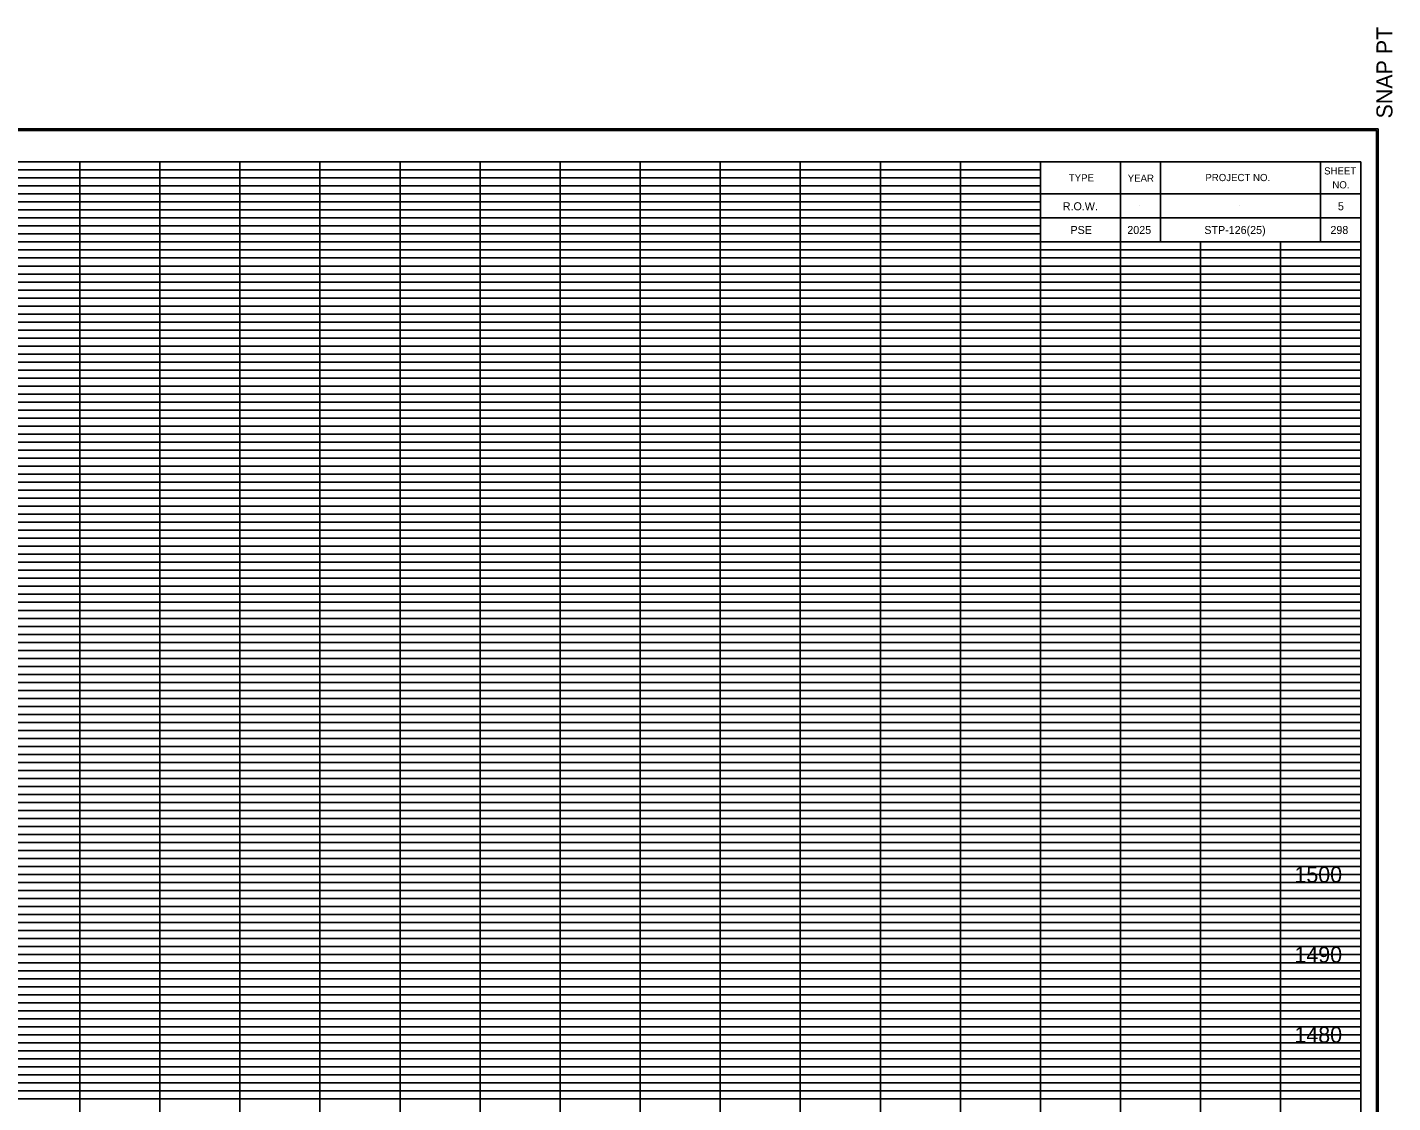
# Model space of a CAD drawing. Extents: x 980 to 2064, y 978 to 2267.
# Drawn here: x 1153.4 to 1324, y 2132.5 to 2266.8 of the extents above; entities that cross this region are included whole.
import ezdxf

# ---------------------------------------------------------------- set-up
doc = ezdxf.new("R2010")
doc.units = 0
for name, color, linetype in [('Default', 7, 'Continuous'), ('DESIGN - SCRATCH - User 1', 7, 'Continuous'), ('DESIGN - SHEET - Corner Text', 7, 'Continuous'), ('DESIGN - SHEET - Light Grid', 7, 'Continuous'), ('DESIGN - SHEET - Linework', 7, 'Continuous'), ('DESIGN - SHEET - Plot Shape', 7, 'Continuous')]:
    doc.layers.add(name, color=color, linetype=linetype)

# ---------------------------------------------------------------- blocks, each defined once
blk = doc.blocks.new('XSTSHT')
at = {"layer": 'DESIGN - SCRATCH - User 1'}
for p, q in [((28.5, 20.45), (28.5, 20.45)), ((29.24, 20.45), (29.24, 20.45)), ((30.49, 20.45), (30.49, 20.45)), ((31.74, 20.45), (31.74, 20.45)), ((28.5, 20.15), (28.5, 20.15)), ((29.24, 20.15), (29.24, 20.15)), ((30.49, 20.15), (30.49, 20.15)), ((31.74, 20.15), (31.74, 20.15))]:
    blk.add_line(p, q, dxfattribs=at)
at = {"layer": 'DESIGN - SHEET - Light Grid'}
for p, q in [((8, 20.9), (16, 20.9)), ((16, 20.9), (24, 20.9)), ((24, 20.9), (28, 20.9)), ((8, 20.8), (16, 20.8)), ((8, 20.7), (16, 20.7)), ((16, 20.8), (24, 20.8)), ((16, 20.7), (24, 20.7)), ((24, 20.8), (28, 20.8)), ((24, 20.7), (28, 20.7)), ((8, 20.6), (16, 20.6)), ((8, 20.5), (16, 20.5)), ((16, 20.6), (24, 20.6)), ((16, 20.5), (24, 20.5)), ((24, 20.6), (28, 20.6)), ((24, 20.5), (28, 20.5)), ((8, 20.4), (16, 20.4)), ((8, 20.3), (16, 20.3)), ((16, 20.4), (24, 20.4)), ((16, 20.3), (24, 20.3)), ((24, 20.4), (28, 20.4)), ((24, 20.3), (28, 20.3)), ((8, 20.2), (16, 20.2)), ((16, 20.2), (24, 20.2)), ((24, 20.2), (28, 20.2)), ((8, 20.1), (16, 20.1)), ((16, 20.1), (24, 20.1)), ((24, 20.1), (28, 20.1)), ((8, 19.9), (16, 19.9)), ((8, 19.8), (16, 19.8)), ((16, 19.9), (24, 19.9)), ((16, 19.8), (24, 19.8)), ((24, 19.9), (32, 19.9)), ((24, 19.8), (32, 19.8)), ((8, 19.7), (16, 19.7)), ((16, 19.7), (24, 19.7)), ((24, 19.7), (32, 19.7)), ((8, 19.6), (16, 19.6)), ((8, 19.5), (16, 19.5)), ((16, 19.6), (24, 19.6)), ((16, 19.5), (24, 19.5)), ((24, 19.6), (32, 19.6)), ((24, 19.5), (32, 19.5)), ((8, 19.4), (16, 19.4)), ((8, 19.3), (16, 19.3)), ((16, 19.4), (24, 19.4)), ((16, 19.3), (24, 19.3)), ((24, 19.4), (32, 19.4)), ((24, 19.3), (32, 19.3)), ((8, 19.2), (16, 19.2)), ((16, 19.2), (24, 19.2)), ((24, 19.2), (32, 19.2)), ((8, 19.1), (16, 19.1)), ((16, 19.1), (24, 19.1)), ((24, 19.1), (32, 19.1)), ((8, 18.9), (16, 18.9)), ((8, 18.8), (16, 18.8)), ((16, 18.9), (24, 18.9)), ((16, 18.8), (24, 18.8)), ((24, 18.9), (32, 18.9)), ((24, 18.8), (32, 18.8)), ((8, 18.7), (16, 18.7)), ((8, 18.6), (16, 18.6)), ((16, 18.7), (24, 18.7)), ((16, 18.6), (24, 18.6)), ((24, 18.7), (32, 18.7)), ((24, 18.6), (32, 18.6)), ((8, 18.5), (16, 18.5)), ((16, 18.5), (24, 18.5)), ((24, 18.5), (32, 18.5)), ((8, 18.4), (16, 18.4)), ((8, 18.3), (16, 18.3)), ((16, 18.4), (24, 18.4)), ((16, 18.3), (24, 18.3)), ((24, 18.4), (32, 18.4)), ((24, 18.3), (32, 18.3)), ((8, 18.2), (16, 18.2)), ((8, 18.1), (16, 18.1)), ((16, 18.2), (24, 18.2)), ((16, 18.1), (24, 18.1)), ((24, 18.2), (32, 18.2)), ((24, 18.1), (32, 18.1)), ((8, 17.9), (16, 17.9)), ((8, 17.8), (16, 17.8)), ((16, 17.9), (24, 17.9)), ((16, 17.8), (24, 17.8)), ((24, 17.9), (32, 17.9)), ((24, 17.8), (32, 17.8)), ((8, 17.7), (16, 17.7)), ((8, 17.6), (16, 17.6)), ((16, 17.7), (24, 17.7)), ((16, 17.6), (24, 17.6)), ((24, 17.7), (32, 17.7)), ((24, 17.6), (32, 17.6)), ((8, 17.5), (16, 17.5)), ((8, 17.4), (16, 17.4)), ((16, 17.5), (24, 17.5)), ((16, 17.4), (24, 17.4)), ((24, 17.5), (32, 17.5)), ((24, 17.4), (32, 17.4)), ((8, 17.3), (16, 17.3)), ((16, 17.3), (24, 17.3)), ((24, 17.3), (32, 17.3)), ((8, 17.2), (16, 17.2)), ((8, 17.1), (16, 17.1)), ((16, 17.2), (24, 17.2)), ((16, 17.1), (24, 17.1)), ((24, 17.2), (32, 17.2)), ((24, 17.1), (32, 17.1)), ((8, 16.9), (16, 16.9)), ((16, 16.9), (24, 16.9)), ((24, 16.9), (32, 16.9)), ((8, 16.8), (16, 16.8)), ((16, 16.8), (24, 16.8)), ((24, 16.8), (32, 16.8)), ((8, 16.7), (16, 16.7)), ((8, 16.6), (16, 16.6)), ((16, 16.7), (24, 16.7)), ((16, 16.6), (24, 16.6)), ((24, 16.7), (32, 16.7)), ((24, 16.6), (32, 16.6)), ((8, 16.5), (16, 16.5)), ((8, 16.4), (16, 16.4)), ((16, 16.5), (24, 16.5)), ((16, 16.4), (24, 16.4)), ((24, 16.5), (32, 16.5)), ((24, 16.4), (32, 16.4)), ((8, 16.3), (16, 16.3)), ((16, 16.3), (24, 16.3)), ((24, 16.3), (32, 16.3)), ((8, 16.2), (16, 16.2)), ((8, 16.1), (16, 16.1)), ((16, 16.2), (24, 16.2)), ((16, 16.1), (24, 16.1)), ((24, 16.2), (32, 16.2)), ((24, 16.1), (32, 16.1)), ((8, 15.9), (16, 15.9)), ((16, 15.9), (24, 15.9)), ((24, 15.9), (32, 15.9)), ((8, 15.8), (16, 15.8)), ((8, 15.7), (16, 15.7)), ((16, 15.8), (24, 15.8)), ((16, 15.7), (24, 15.7)), ((24, 15.8), (32, 15.8)), ((24, 15.7), (32, 15.7)), ((8, 15.6), (16, 15.6)), ((16, 15.6), (24, 15.6)), ((24, 15.6), (32, 15.6)), ((8, 15.5), (16, 15.5)), ((8, 15.4), (16, 15.4)), ((16, 15.5), (24, 15.5)), ((16, 15.4), (24, 15.4)), ((24, 15.5), (32, 15.5)), ((24, 15.4), (32, 15.4)), ((8, 15.3), (16, 15.3)), ((8, 15.2), (16, 15.2)), ((16, 15.3), (24, 15.3)), ((16, 15.2), (24, 15.2)), ((24, 15.3), (32, 15.3)), ((24, 15.2), (32, 15.2)), ((8, 15.1), (16, 15.1)), ((16, 15.1), (24, 15.1)), ((24, 15.1), (32, 15.1)), ((8, 14.9), (16, 14.9)), ((16, 14.9), (24, 14.9)), ((24, 14.9), (32, 14.9)), ((8, 14.8), (16, 14.8)), ((8, 14.7), (16, 14.7)), ((16, 14.8), (24, 14.8)), ((16, 14.7), (24, 14.7)), ((24, 14.8), (32, 14.8)), ((24, 14.7), (32, 14.7)), ((8, 14.6), (16, 14.6)), ((8, 14.5), (16, 14.5)), ((16, 14.6), (24, 14.6)), ((16, 14.5), (24, 14.5)), ((24, 14.6), (32, 14.6)), ((24, 14.5), (32, 14.5)), ((8, 14.4), (16, 14.4)), ((16, 14.4), (24, 14.4)), ((24, 14.4), (32, 14.4)), ((8, 14.3), (16, 14.3)), ((8, 14.2), (16, 14.2)), ((16, 14.3), (24, 14.3)), ((16, 14.2), (24, 14.2)), ((24, 14.3), (32, 14.3)), ((24, 14.2), (32, 14.2)), ((8, 14.1), (16, 14.1)), ((16, 14.1), (24, 14.1)), ((24, 14.1), (32, 14.1)), ((8, 13.9), (16, 13.9)), ((16, 13.9), (24, 13.9)), ((24, 13.9), (32, 13.9)), ((8, 13.8), (16, 13.8)), ((8, 13.7), (16, 13.7)), ((16, 13.8), (24, 13.8)), ((16, 13.7), (24, 13.7)), ((24, 13.8), (32, 13.8)), ((24, 13.7), (32, 13.7)), ((8, 13.6), (16, 13.6)), ((8, 13.5), (16, 13.5)), ((16, 13.6), (24, 13.6)), ((16, 13.5), (24, 13.5)), ((24, 13.6), (32, 13.6)), ((24, 13.5), (32, 13.5)), ((8, 13.4), (16, 13.4)), ((16, 13.4), (24, 13.4)), ((24, 13.4), (32, 13.4)), ((8, 13.3), (16, 13.3)), ((8, 13.2), (16, 13.2)), ((16, 13.3), (24, 13.3)), ((16, 13.2), (24, 13.2)), ((24, 13.3), (32, 13.3)), ((24, 13.2), (32, 13.2)), ((8, 13.1), (16, 13.1)), ((16, 13.1), (24, 13.1)), ((24, 13.1), (32, 13.1)), ((8, 12.9), (16, 12.9)), ((8, 12.8), (16, 12.8)), ((16, 12.9), (24, 12.9)), ((16, 12.8), (24, 12.8)), ((24, 12.9), (32, 12.9)), ((24, 12.8), (32, 12.8)), ((8, 12.7), (16, 12.7)), ((16, 12.7), (24, 12.7)), ((24, 12.7), (32, 12.7)), ((8, 12.6), (16, 12.6)), ((8, 12.5), (16, 12.5)), ((16, 12.6), (24, 12.6)), ((16, 12.5), (24, 12.5)), ((24, 12.6), (32, 12.6)), ((24, 12.5), (32, 12.5)), ((8, 12.4), (16, 12.4)), ((8, 12.3), (16, 12.3)), ((16, 12.4), (24, 12.4)), ((16, 12.3), (24, 12.3)), ((24, 12.4), (32, 12.4)), ((24, 12.3), (32, 12.3)), ((8, 12.2), (16, 12.2)), ((16, 12.2), (24, 12.2)), ((24, 12.2), (32, 12.2)), ((8, 12.1), (16, 12.1)), ((16, 12.1), (24, 12.1)), ((24, 12.1), (32, 12.1)), ((8, 11.9), (16, 11.9)), ((8, 11.8), (16, 11.8)), ((16, 11.9), (24, 11.9)), ((16, 11.8), (24, 11.8)), ((24, 11.9), (32, 11.9)), ((24, 11.8), (32, 11.8)), ((8, 11.7), (16, 11.7)), ((8, 11.6), (16, 11.6)), ((16, 11.7), (24, 11.7)), ((16, 11.6), (24, 11.6)), ((24, 11.7), (32, 11.7)), ((24, 11.6), (32, 11.6)), ((8, 11.5), (16, 11.5)), ((16, 11.5), (24, 11.5)), ((24, 11.5), (32, 11.5)), ((8, 11.4), (16, 11.4)), ((8, 11.3), (16, 11.3)), ((16, 11.4), (24, 11.4)), ((16, 11.3), (24, 11.3)), ((24, 11.4), (32, 11.4)), ((24, 11.3), (32, 11.3)), ((8, 11.2), (16, 11.2)), ((8, 11.1), (16, 11.1)), ((16, 11.2), (24, 11.2)), ((16, 11.1), (24, 11.1)), ((24, 11.2), (32, 11.2)), ((24, 11.1), (32, 11.1)), ((8, 10.9), (16, 10.9)), ((8, 10.8), (16, 10.8)), ((16, 10.9), (24, 10.9)), ((16, 10.8), (24, 10.8)), ((24, 10.9), (32, 10.9)), ((24, 10.8), (32, 10.8)), ((8, 10.7), (16, 10.7)), ((8, 10.6), (16, 10.6)), ((16, 10.7), (24, 10.7)), ((16, 10.6), (24, 10.6)), ((24, 10.7), (32, 10.7)), ((24, 10.6), (32, 10.6)), ((8, 10.5), (16, 10.5)), ((16, 10.5), (24, 10.5)), ((24, 10.5), (32, 10.5)), ((8, 10.4), (16, 10.4)), ((8, 10.3), (16, 10.3)), ((16, 10.4), (24, 10.4)), ((16, 10.3), (24, 10.3)), ((24, 10.4), (32, 10.4)), ((24, 10.3), (32, 10.3)), ((8, 10.2), (16, 10.2)), ((8, 10.1), (16, 10.1)), ((16, 10.2), (24, 10.2)), ((16, 10.1), (24, 10.1)), ((24, 10.2), (32, 10.2)), ((24, 10.1), (32, 10.1)), ((8, 9.9), (16, 9.9)), ((16, 9.9), (24, 9.9)), ((24, 9.9), (32, 9.9)), ((8, 9.8), (16, 9.8)), ((16, 9.8), (24, 9.8)), ((24, 9.8), (32, 9.8)), ((8, 9.7), (16, 9.7)), ((8, 9.6), (16, 9.6)), ((16, 9.7), (24, 9.7)), ((16, 9.6), (24, 9.6)), ((24, 9.7), (32, 9.7)), ((24, 9.6), (32, 9.6)), ((8, 9.5), (16, 9.5)), ((8, 9.4), (16, 9.4)), ((16, 9.5), (24, 9.5)), ((16, 9.4), (24, 9.4)), ((24, 9.5), (32, 9.5)), ((24, 9.4), (32, 9.4)), ((8, 9.3), (16, 9.3)), ((16, 9.3), (24, 9.3)), ((24, 9.3), (32, 9.3))]:
    blk.add_line(p, q, dxfattribs=at)
at = {"layer": 'DESIGN - SHEET - Linework'}
for p, q in [((-1.823, 21.414), (32.217, 21.414)), ((32.217, 21.414), (32.217, -0.414)), ((16, 0), (16, 21)), ((17, 0), (17, 21)), ((18, 0), (18, 21)), ((19, 0), (19, 21)), ((20, 0), (20, 21)), ((21, 0), (21, 21)), ((22, 0), (22, 21)), ((23, 0), (23, 21)), ((24, 0), (24, 21)), ((25, 0), (25, 21)), ((26, 0), (26, 21)), ((27, 0), (27, 21)), ((0, 20), (28, 20)), ((28, 0), (28, 20)), ((29, 0), (29, 20)), ((30, 0), (30, 20)), ((31, 0), (31, 20)), ((0, 19), (32, 19)), ((0, 18), (32, 18)), ((0, 17), (32, 17)), ((0, 16), (32, 16)), ((0, 15), (32, 15)), ((0, 14), (32, 14)), ((0, 13), (32, 13)), ((0, 12), (32, 12)), ((0, 11), (32, 11)), ((0, 10), (32, 10))]:
    blk.add_line(p, q, dxfattribs=at)
for points in [[(0, 21), (0, 0), (32, 0), (32, 21), (0, 21)], [(28, 21), (28, 20), (32, 20), (32, 21), (31.5, 21), (31.5, 20), (29.5, 20), (29.5, 21), (29, 21), (29, 20), (32, 20), (28, 20), (28, 20.3), (32, 20.3), (32, 20.6), (28, 20.6)]]:
    blk.add_lwpolyline(points, dxfattribs=at)
at = {"layer": 'DESIGN - SHEET - Plot Shape'}
for points in [[(-1.803, 21.394), (32.197, 21.394), (32.197, -0.394), (-1.803, -0.394)], [(-0.85, 21), (32, 21), (32, -0.25), (-0.85, -0.25)]]:
    blk.add_lwpolyline(points, close=True, dxfattribs=at)
at = {"layer": 'DESIGN - SHEET - Corner Text'}
blk.add_text('  SNAP PT', height=0.2, rotation=90, dxfattribs=at).set_placement((32.397, 21.394))
for s, p in [('TYPE', (28.354, 20.756)), ('YEAR', (29.09, 20.752)), ('PROJECT NO.', (30.06, 20.76)), ('SHEET', (31.543, 20.843)), ('NO.', (31.646, 20.669))]:
    blk.add_text(s, height=0.09, dxfattribs=at).set_placement(p)

msp = doc.modelspace()

# ---------------------------------------------------------------- block references
at = {"layer": 'Default', "xscale": 10, "yscale": 10}
msp.add_blockref('XSTSHT', (1000, 2040), dxfattribs=at)

# ---------------------------------------------------------------- texts
at = {"layer": 'Default'}
for s, p in [('     1500     ', (1308.01, 2160)), ('     1490     ', (1308.01, 2150)), ('     1480     ', (1308.01, 2140))]:
    msp.add_text(s, height=2, dxfattribs=at).set_placement(p)
at = {"layer": 'DESIGN - SHEET - Corner Text'}
for s, p in [('R.O.W.', (1282.79, 2243.96)), ('5', (1317.16, 2243.96)), ('PSE', (1283.75, 2241)), ('2025', (1290.85, 2241)), ('STP-126(25)', (1300.47, 2241)), ('298', (1316.22, 2241))]:
    msp.add_text(s, height=1, dxfattribs=at).set_placement(p)

doc.saveas('drawing.dxf')
